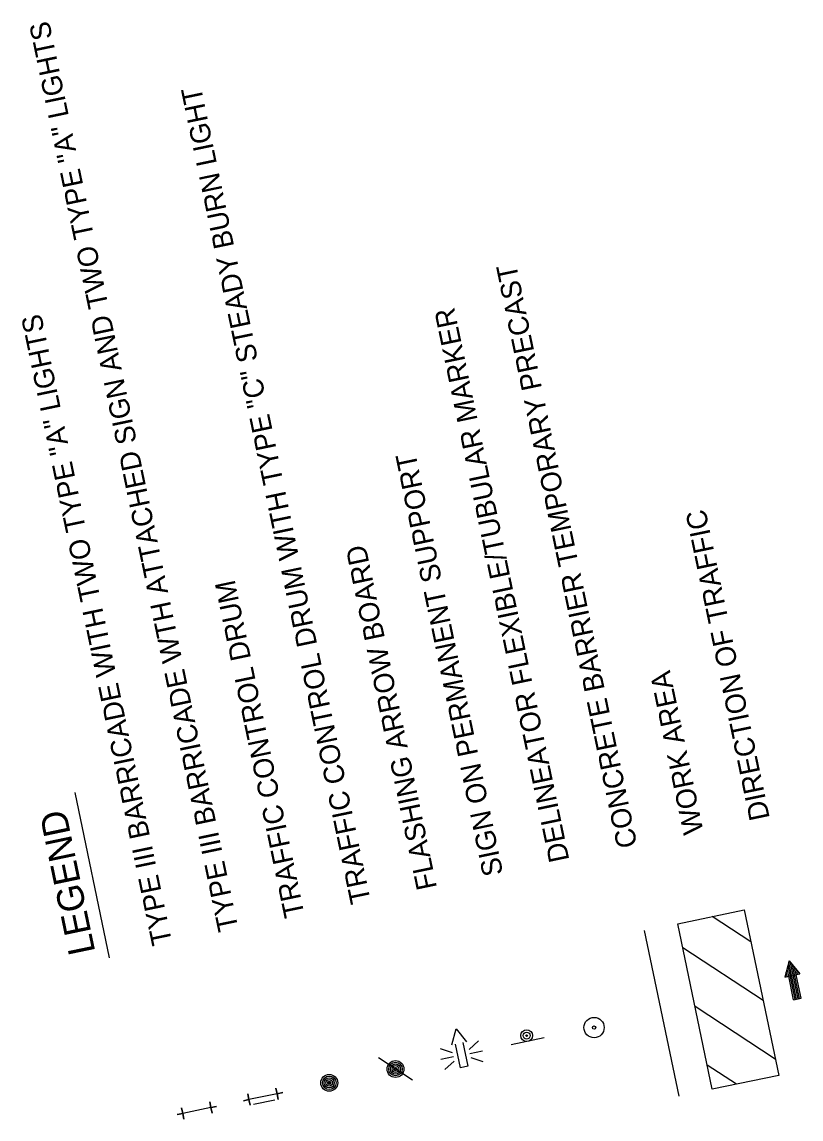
# Model space of a CAD drawing. Extents: x 361654 to 361884, y 127138 to 127463.
import ezdxf

# ---------------------------------------------------------------- set-up
doc = ezdxf.new("R2010")
doc.units = 0
for name, color, linetype in [('P_TC', 7, 'Continuous'), ('P_TC_BarrierConc', 7, 'Continuous'), ('P_TC_FlowArrow', 7, 'Continuous'), ('P_TC_Text', 7, 'Continuous')]:
    doc.layers.add(name, color=color, linetype=linetype)

msp = doc.modelspace()

# ---------------------------------------------------------------- linework, layer by layer
at = {"layer": 'P_TC'}
for p, q in [((361869.17, 127190.67), (361857.7, 127198.18)), ((361872.78, 127173.36), (361849.06, 127188.9)), ((361876.4, 127156.06), (361852.67, 127171.59)), ((361780.7, 127160.22), (361781.97, 127164.97)), ((361781.97, 127164.97), (361785.1, 127161.14)), ((361808.07, 127162.29), (361798.28, 127160.25)), ((361780.91, 127157.9), (361777.35, 127159.07)), ((361783.26, 127153.47), (361781.8, 127160.45)), ((361784, 127160.91), (361785.46, 127153.93)), ((361785.84, 127158.93), (361788.63, 127161.43)), ((361769.1, 127149.8), (361759, 127156.41)), ((361781.17, 127156.68), (361777.49, 127155.91)), ((361786.09, 127157.7), (361789.76, 127158.47)), ((361786.35, 127156.48), (361789.91, 127155.31)), ((361781.42, 127155.45), (361778.62, 127152.95)), ((361785.46, 127153.93), (361783.26, 127153.47)), ((361864.94, 127148.62), (361856.28, 127154.29)), ((361728.71, 127147.47), (361729.05, 127145.81)), ((361729.05, 127145.81), (361728.71, 127147.47)), ((361729.05, 127145.81), (361730.72, 127146.15)), ((361730.72, 127146.15), (361729.05, 127145.81)), ((361709.13, 127143.38), (361709.48, 127141.72)), ((361709.48, 127141.72), (361709.13, 127143.38)), ((361720.73, 127144.07), (361719.07, 127143.72)), ((361719.07, 127143.72), (361720.73, 127144.07)), ((361720.73, 127144.07), (361720.39, 127145.73)), ((361720.39, 127145.73), (361720.73, 127144.07)), ((361729.05, 127145.81), (361720.73, 127144.07)), ((361720.73, 127144.07), (361721.08, 127142.41)), ((361721.08, 127142.41), (361720.73, 127144.07)), ((361728.42, 127143.94), (361722.06, 127142.61)), ((361729.05, 127145.81), (361729.4, 127144.14)), ((361729.4, 127144.14), (361729.05, 127145.81)), ((361701.15, 127139.98), (361699.49, 127139.64)), ((361699.49, 127139.64), (361701.15, 127139.98)), ((361701.15, 127139.98), (361700.81, 127141.65)), ((361700.81, 127141.65), (361701.15, 127139.98)), ((361709.48, 127141.72), (361701.15, 127139.98)), ((361701.15, 127139.98), (361701.5, 127138.32)), ((361701.5, 127138.32), (361701.15, 127139.98)), ((361709.48, 127141.72), (361711.14, 127142.07)), ((361711.14, 127142.07), (361709.48, 127141.72)), ((361709.48, 127141.72), (361709.82, 127140.06)), ((361709.82, 127140.06), (361709.48, 127141.72))]:
    msp.add_line(p, q, dxfattribs=at)
msp.add_lwpolyline([(361857.77, 127147.12), (361847.56, 127196.07), (361867.19, 127200.16), (361877.41, 127151.22)], close=True, dxfattribs=at)
for centre, radius in [((361822.79, 127165.36), 3), ((361822.79, 127165.36), 0.5), ((361802.85, 127162.99), 1.75), ((361802.85, 127162.99), 1), ((361802.85, 127162.99), 0.25), ((361764.05, 127153.11), 2.5), ((361764.05, 127153.11), 2), ((361764.05, 127153.11), 1.5), ((361764.05, 127153.11), 1), ((361764.05, 127153.11), 0.5), ((361764.05, 127153.11), 0.25), ((361744.47, 127149.02), 2.5), ((361744.47, 127149.02), 2), ((361744.47, 127149.02), 1.5), ((361744.47, 127149.02), 1), ((361744.47, 127149.02), 0.5), ((361744.47, 127149.02), 0.25)]:
    msp.add_circle(centre, radius, dxfattribs=at)
at = {"layer": 'P_TC_BarrierConc'}
msp.add_line((361847.96, 127145.07), (361837.75, 127194.02), dxfattribs=at)
at = {"layer": 'P_TC_FlowArrow'}
for p, q in [((361880.53, 127185.07), (361879.26, 127180.31)), ((361880.53, 127185.07), (361883.66, 127181.23)), ((361879.92, 127180.48), (361879.65, 127181.76)), ((361880.36, 127180.57), (361879.91, 127182.73)), ((361882.26, 127173.66), (361880.16, 127183.69)), ((361882.7, 127173.75), (361880.42, 127184.66)), ((361883.14, 127173.85), (361880.89, 127184.63)), ((361883.58, 127173.94), (361881.5, 127183.88)), ((361882.56, 127181.03), (361882.12, 127183.12)), ((361883, 127181.12), (361882.74, 127182.37)), ((361883.44, 127181.21), (361883.36, 127181.61)), ((361879.26, 127180.31), (361883.66, 127181.23)), ((361879.47, 127180.38), (361879.39, 127180.8)), ((361881.82, 127173.57), (361880.36, 127180.54)), ((361884.02, 127174.03), (361882.56, 127181)), ((361881.82, 127173.57), (361884.02, 127174.03)), ((361882.92, 127173.8), (361882.92, 127173.8))]:
    msp.add_line(p, q, dxfattribs=at)
at = {"layer": 'P_TC_Text'}
msp.add_line((361679.48, 127186.01), (361669.29, 127234.86), dxfattribs=at)

# ---------------------------------------------------------------- texts
for s, height, p in [('TYPE III BARRICADE WTH ATTACHED SIGN AND TWO TYPE "A" LIGHTS', 6, (361717.62, 127194.5)), ('TRAFFIC CONTROL DRUM WITH TYPE "C" STEADY BURN LIGHT', 6, (361756.78, 127202.67)), ('CONCRETE BARRIER TEMPORARY PRECAST', 6, (361835.63, 127219.12)), ('DELINEATOR FLEXIBLE/TUBULAR MARKER', 6, (361815.51, 127214.92)), ('TYPE III BARRICADE WITH TWO TYPE "A" LIGHTS', 6, (361698.04, 127190.41)), ('SIGN ON PERMANENT SUPPORT', 6, (361795.93, 127210.83)), ('DIRECTION OF TRAFFIC', 6, (361874.79, 127227.28)), ('FLASHING ARROW BOARD', 6, (361776.35, 127206.75)), ('TRAFFIC CONTROL DRUM', 6, (361737.2, 127198.58)), ('WORK AREA', 6, (361855.21, 127223.2)), ('LEGEND', 7.88, (361675.3, 127187.77))]:
    msp.add_text(s, height=height, rotation=101.7841, dxfattribs=at).set_placement(p)

doc.saveas('drawing.dxf')
